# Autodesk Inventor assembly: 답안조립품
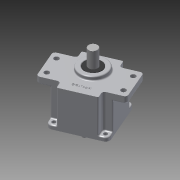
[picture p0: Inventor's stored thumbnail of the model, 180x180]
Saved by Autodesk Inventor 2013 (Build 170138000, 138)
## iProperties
Created: 2015-07
Part Number: 답안조립품
Document SubType Name: Assembly
Designer: user
Author: user
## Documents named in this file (12)
- C:\Users\user\Desktop\450734V1014\답안조립품.iam
- C:\Users\user\Desktop\450734V1014\메인축.ipt
- C:\Users\user\Desktop\450734V1014\베어링 608.ipt
- 베어링 608.ipt
- C:\Users\user\Desktop\450734V1014\베어링 6003.ipt
- 베어링 6003.ipt
- C:\Users\user\Desktop\450734V1014\서브축.ipt
- C:\Users\user\Desktop\450734V1014\본체.ipt
- C:\Users\user\Desktop\450734V1014\커버.ipt
- C:\Users\user\Desktop\450734V1014\오일실 8x22x7.ipt
- C:\Users\user\Desktop\450734V1014\오일실 17x32x8.ipt
- C:\Users\user\Desktop\450734V1014\M4x0.5x16.ipt
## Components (4 placed, 1 different names)
1. M4x0.5x12:1
2. M4x0.5x12:2
3. M4x0.5x12:3
4. M4x0.5x12:4
